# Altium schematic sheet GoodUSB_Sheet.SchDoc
size A4
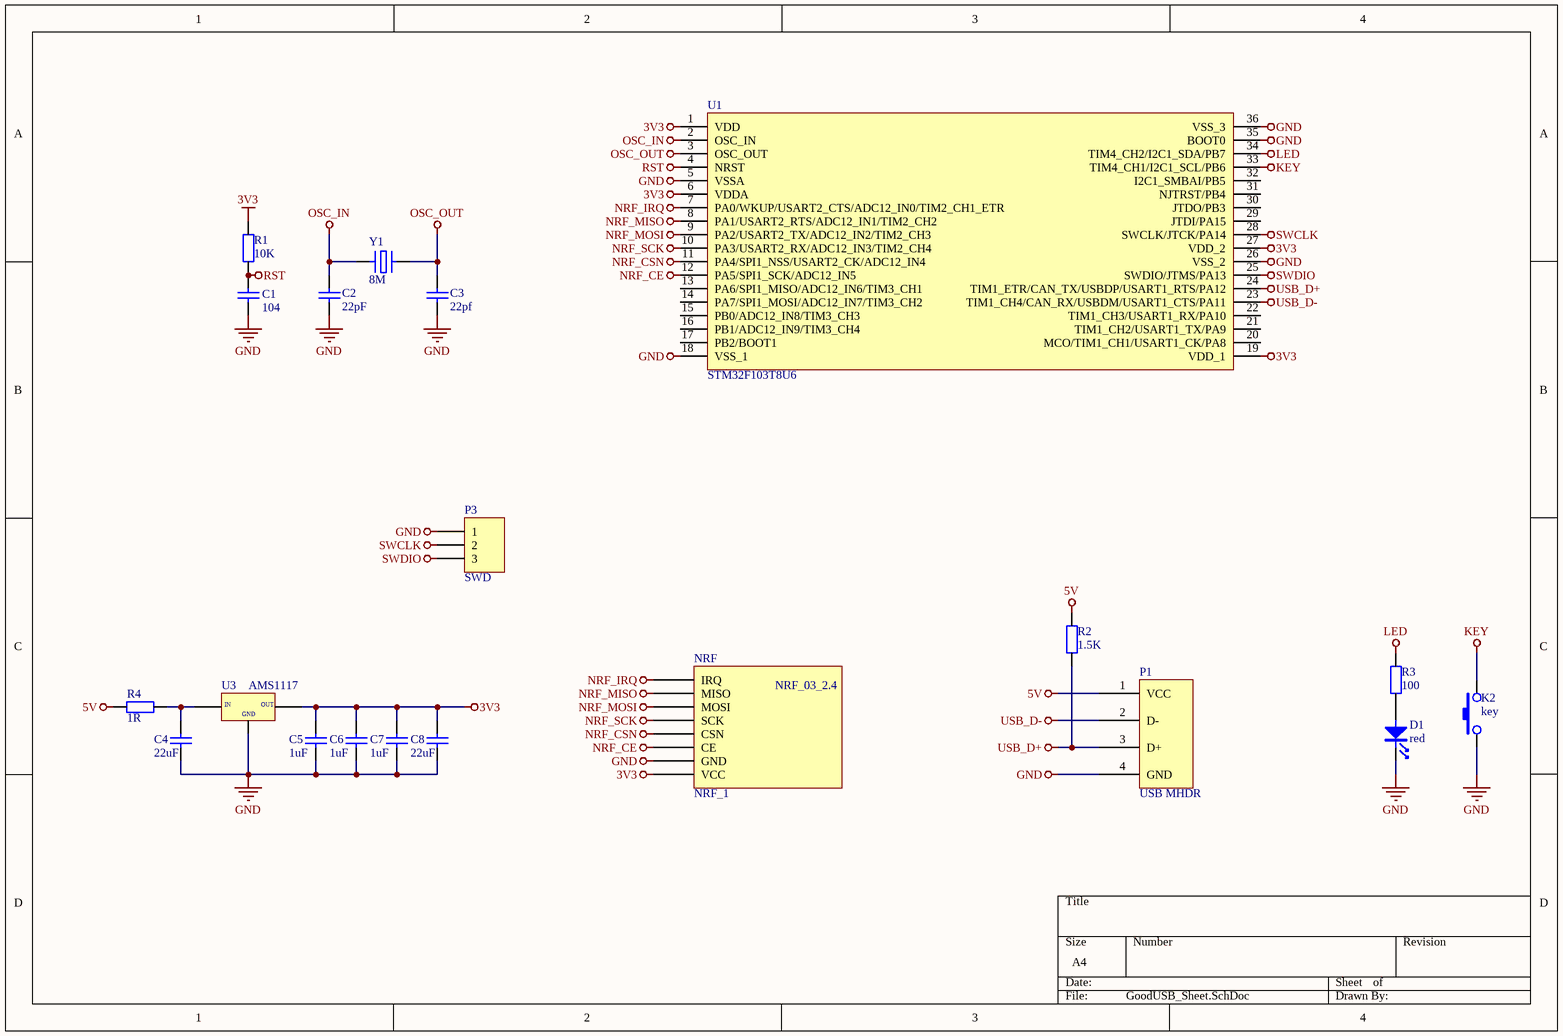
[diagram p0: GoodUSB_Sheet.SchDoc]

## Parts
C1  104  [电容_C0603]
C2  22pF  [电容_C0603]
C3  22pf  [电容_C0603]
C4  22uF  [电容_C1206]
C5  1uF  [电容_C0603]
C6  1uF  [电容_C0603]
C7  1uF  [电容_C0603]
C8  22uF  [电容_C1206]
D1  red  [LED_0603]
K2  key  [开关按键_SKTH]
NRF  NRF_1  [NRF-1]
P1  USB MHDR  [接插件_USB 公头 90°]
P3  SWD  [HDR1X3]
R1  10K  [电阻_R0603]
R2  1.5K  [电阻_R0603]
R3  100  [电阻_R0603]
R4  1R  [电阻_R0603]
U1  STM32F103T8U6  [ST主控_VFQFPN36]
U3  AMS1117  [稳压芯片_SOT-89]
Y1  F: 8M  [晶振_5032]  (hidden comment: XTAL)

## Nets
3V3: C5.2 C6.2 C7.2 C8.2 NRF.1(VCC) R1.2 U1.1(VDD) U1.6(VDDA) U1.19(VDD_1) U1.27(VDD_2) U3.2(OUT)
5V: P1.1(VCC) R2.1 R4.2
GND: C1.1 C2.2 C3.2 C4.1 C5.1 C6.1 C7.1 C8.1 D1.K K2.1 NRF.2(GND) P1.0(GND) P1.4(GND) P3.1 U1.5(VSSA) U1.18(VSS_1) U1.26(VSS_2) U1.35(BOOT0) U1.36(VSS_3) U3.1(GND)
KEY: K2.2 U1.33(TIM4_CH1/I2C1_SCL/PB6)
LED: R3.1 U1.34(TIM4_CH2/I2C1_SDA/PB7)
NRF_CE: NRF.3(CE) U1.12(PA5/SPI1_SCK/ADC12_IN5)
NRF_CSN: NRF.4(CSN) U1.11(PA4/SPI1_NSS/USART2_CK/ADC12_IN4)
NRF_IRQ: NRF.8(IRQ) U1.7(PA0/WKUP/USART2_CTS/ADC12_IN0/TIM2_CH1_ETR)
NRF_MISO: NRF.7(MISO) U1.8(PA1/USART2_RTS/ADC12_IN1/TIM2_CH2)
NRF_MOSI: NRF.6(MOSI) U1.9(PA2/USART2_TX/ADC12_IN2/TIM2_CH3)
NRF_SCK: NRF.5(SCK) U1.10(PA3/USART2_RX/ADC12_IN3/TIM2_CH4)
OSC_IN: C2.1 U1.2(OSC_IN) Y1.1
OSC_OUT: C3.1 U1.3(OSC_OUT) Y1.2
RST: C1.2 R1.1 U1.4(NRST)
SWCLK: P3.2 U1.28(SWCLK/JTCK/PA14)
SWDIO: P3.3 U1.25(SWDIO/JTMS/PA13)
USB_D+: P1.3(D+) R2.2 U1.24(TIM1_ETR/CAN_TX/USBDP/USART1_RTS/PA12)
USB_D-: P1.2(D-) U1.23(TIM1_CH4/CAN_RX/USBDM/USART1_CTS/PA11)
NetC4_2: C4.2 R4.1 U3.3(VIN)
NetD1_A: D1.A R3.2

Not connected (* = marked no-connect by the designer): U1 13(PA6/SPI1_MISO/ADC12_IN6/TIM3_CH1) 14(PA7/SPI1_MOSI/ADC12_IN7/TIM3_CH2) 15(PB0/ADC12_IN8/TIM3_CH3) 16(PB1/ADC12_IN9/TIM3_CH4) 17(PB2/BOOT1) 20(MCO/TIM1_CH1/USART1_CK/PA8) 21(TIM1_CH2/USART1_TX/PA9) 22(TIM1_CH3/USART1_RX/PA10) 29(JTDI/PA15) 30(JTDO/PB3) 31(NJTRST/PB4) 32(I2C1_SMBAI/PB5)

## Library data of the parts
C1-C8 = cap: U: 50V; 参数: Cap,0805,X7R,104K,50V,125C,±10%
D1 = LED: 参数: LED,0603,Red
K2 = SW-PB: 参数: Key,TS-018A 2*4全包无柱带支架 力度250N; 备注: ADD
P3 = Header 3: Header, 3-Pin
R1-R4 = Res: P: 1/8W; 参数: Res,0805,0R,±1%,1/8W,100ppm,155C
